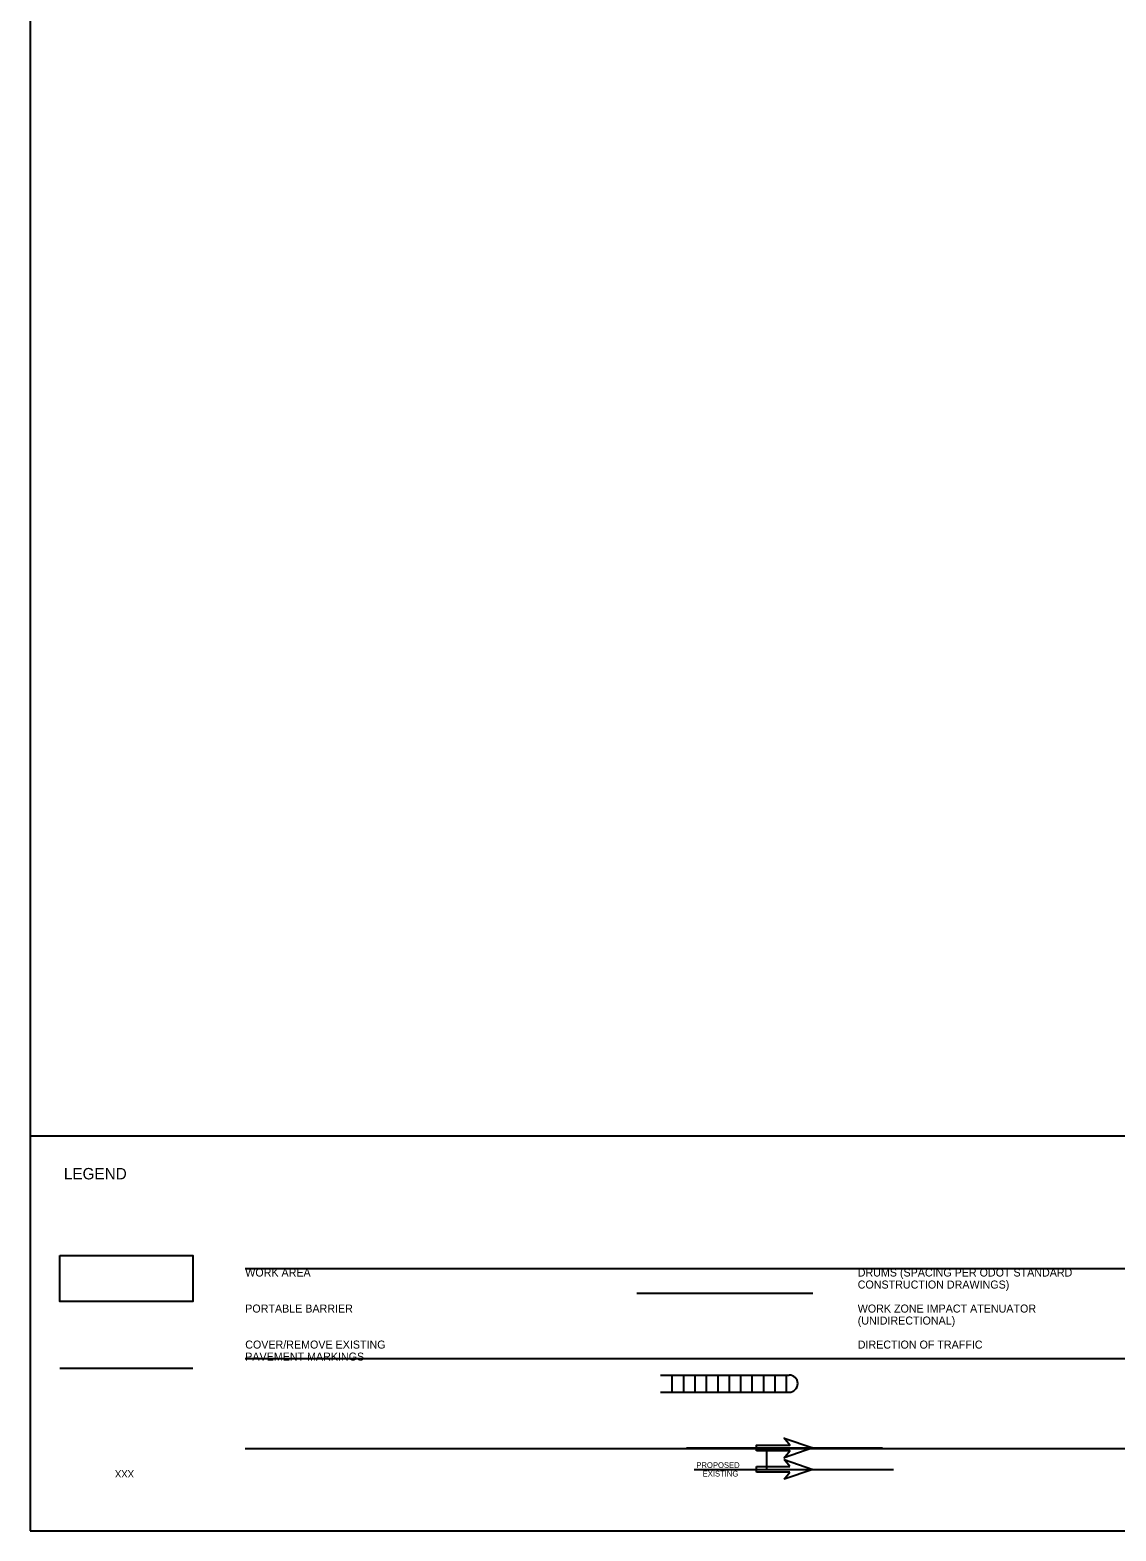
# Model space of a CAD drawing. Extents: x 75 to 1600, y 25 to 1075.
# Drawn here: x 75 to 455, y 25 to 550 of the extents above; entities that cross this region are included whole.
import ezdxf

# ---------------------------------------------------------------- set-up
doc = ezdxf.new("R2010")
doc.units = 0
for name, color, linetype in [('Default', 7, 'Continuous'), ('MT_P_Drums', 7, 'Continuous'), ('MT_P_PCB', 7, 'Continuous'), ('SC_Scratch1', 7, 'Continuous'), ('SC_Scratch2', 7, 'Continuous'), ('SH_Text', 7, 'Continuous')]:
    doc.layers.add(name, color=color, linetype=linetype)

msp = doc.modelspace()

# ---------------------------------------------------------------- linework, layer by layer
at = {"layer": 'Default'}
for p, q in [((295.65, 79.55), (340.65, 79.55)), ((299.65, 79.55), (299.65, 73.55)), ((303.65, 79.55), (303.65, 73.55)), ((307.65, 79.55), (307.65, 73.55)), ((311.65, 79.55), (311.65, 73.55)), ((315.65, 79.55), (315.65, 73.55)), ((319.65, 79.55), (319.65, 73.55)), ((323.65, 79.55), (323.65, 73.55)), ((327.65, 79.55), (327.65, 73.55)), ((331.65, 79.55), (331.65, 73.55)), ((335.65, 79.55), (335.65, 73.55)), ((339.65, 79.55), (339.65, 73.55)), ((295.65, 73.55), (340.65, 73.55)), ((329.26, 53.05), (329.26, 55.05)), ((329.26, 55.05), (340.92, 55.05)), ((340.92, 53.05), (329.26, 53.05)), ((340.92, 55.05), (338.92, 57.52)), ((338.92, 57.52), (348.92, 54.05)), ((348.92, 54.05), (338.92, 50.57)), ((338.92, 50.57), (340.92, 53.05)), ((329.26, 45.55), (329.26, 47.55)), ((329.26, 47.55), (340.92, 47.55)), ((340.92, 47.55), (338.92, 50.02)), ((338.92, 50.02), (348.92, 46.55)), ((340.92, 45.55), (329.26, 45.55)), ((348.92, 46.55), (338.92, 43.07)), ((338.92, 43.07), (340.92, 45.55))]:
    msp.add_line(p, q, dxfattribs=at)
msp.add_lwpolyline([(329.26, 53.05), (329.26, 55.05), (340.92, 55.05), (338.92, 57.52), (348.92, 54.05), (338.92, 50.57), (340.92, 53.05)], close=True, dxfattribs=at)
for start in [90, 270]:
    msp.add_arc((340.65, 76.55), 3, start, 90, dxfattribs=at)
at = {"layer": 'MT_P_Drums'}
msp.add_line((348.92, 108.05), (287.38, 108.05), dxfattribs=at)
at = {"layer": 'MT_P_PCB'}
msp.add_line((131.98, 81.8), (85.46, 81.8), dxfattribs=at)
at = {"layer": 'SC_Scratch1'}
for points in [[(75, 25), (1600, 25), (1600, 1075), (75, 1075)], [(75, 25), (1600, 25), (1600, 163.11), (75, 163.11)]]:
    msp.add_lwpolyline(points, close=True, dxfattribs=at)
at = {"layer": 'SC_Scratch2'}
for p, q in [((150.32, 116.8), (728.57, 116.8)), ((150.32, 85.3), (733.02, 85.3)), ((150.32, 53.8), (753.76, 53.8)), ((304.71, 54.05), (373.29, 54.05)), ((332.89, 46.55), (332.89, 54.05)), ((307.46, 46.55), (377.18, 46.55))]:
    msp.add_line(p, q, dxfattribs=at)
at = {"layer": 'SH_Text'}
msp.add_lwpolyline([(85.46, 121.3), (131.98, 121.3), (131.98, 105.29), (85.46, 105.29)], close=True, dxfattribs=at)

# ---------------------------------------------------------------- texts
for s, height, p in [('LEGEND', 4, (86.86, 147.97)), ('WORK AREA', 2.8, (150.32, 114)), ('DRUMS (SPACING PER ODOT STANDARD', 2.8, (364.66, 114)), ('CONSTRUCTION DRAWINGS)', 2.8, (364.66, 109.8)), ('PORTABLE BARRIER', 2.8, (150.32, 101.4)), ('WORK ZONE IMPACT ATENUATOR', 2.8, (364.66, 101.4)), ('(UNIDIRECTIONAL)', 2.8, (364.66, 97.2)), ('COVER/REMOVE EXISTING ', 2.8, (150.32, 88.8)), ('DIRECTION OF TRAFFIC', 2.8, (364.66, 88.8)), ('PAVEMENT MARKINGS', 2.8, (150.32, 84.6)), ('PROPOSED', 2, (308.18, 47.05)), ('EXISTING', 2, (310.39, 44.05))]:
    msp.add_text(s, height=height, dxfattribs=at).set_placement(p)
msp.add_text('XXX', height=2.5, rotation=180, dxfattribs=at).set_placement((111.41, 46.3))

doc.saveas('drawing.dxf')
